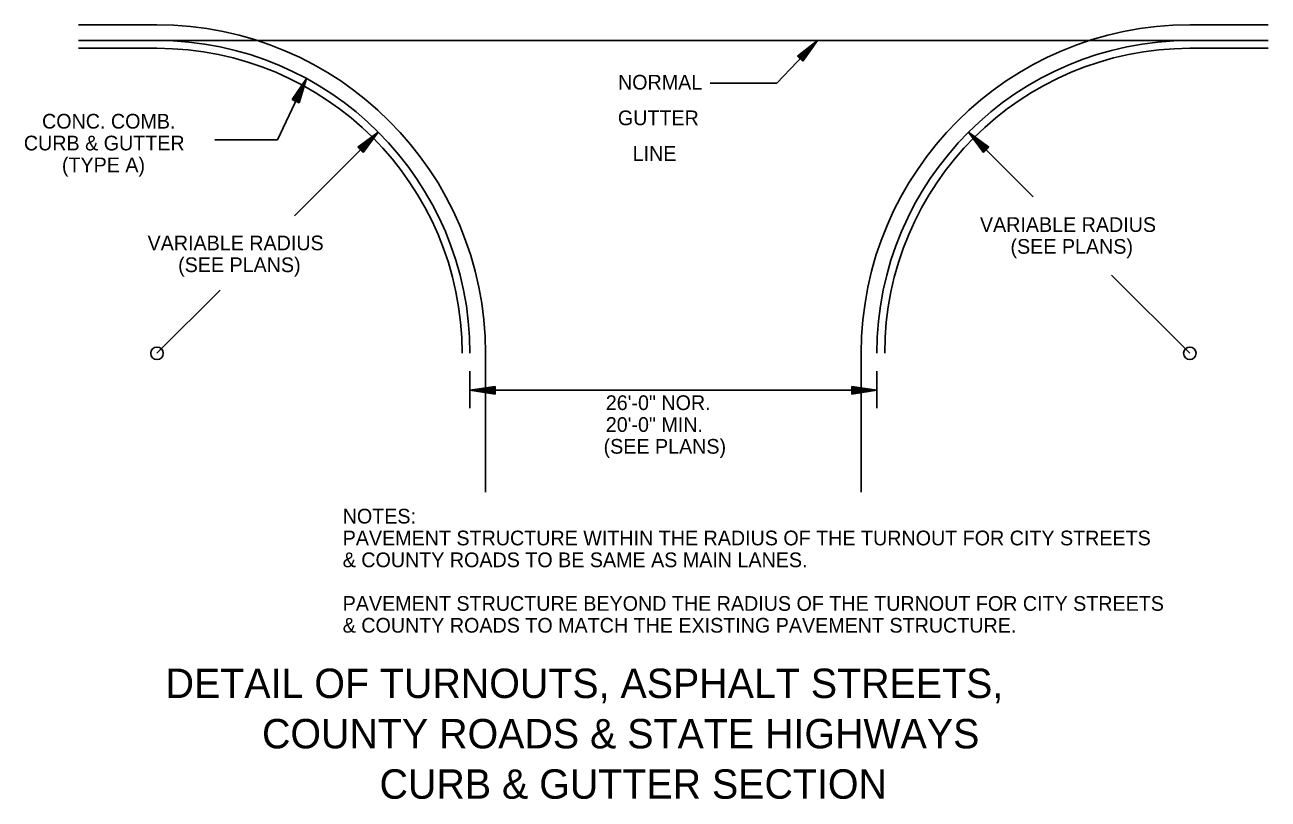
# Model space of a CAD drawing. Extents: x 635488 to 635865, y 290537 to 290973.
# Drawn here: x 635814.4 to 635865.1, y 290707.3 to 290738.9 of the extents above; entities that cross this region are included whole.
import ezdxf

# ---------------------------------------------------------------- set-up
doc = ezdxf.new("R2010")
doc.units = 0
doc.layers.add('Default', color=7, linetype='Continuous')

msp = doc.modelspace()

# ---------------------------------------------------------------- linework, layer by layer
at = {"layer": 'Default'}
for p, q in [((635819.756, 290738.928), (635816.565, 290738.928)), ((635861.865, 290738.928), (635865.054, 290738.928)), ((635840.808, 290738.292), (635816.565, 290738.292)), ((635840.808, 290738.292), (635865.054, 290738.292)), ((635845.024, 290736.544), (635846.685, 290738.292)), ((635845.871, 290737.656), (635846.685, 290738.292)), ((635846.09, 290737.448), (635846.685, 290738.292)), ((635819.756, 290737.973), (635816.565, 290737.973)), ((635845.887, 290737.637), (635846.566, 290738.168)), ((635845.907, 290737.622), (635846.445, 290738.04)), ((635845.925, 290737.602), (635846.329, 290737.917)), ((635845.945, 290737.585), (635846.209, 290737.791)), ((635846.018, 290737.515), (635846.209, 290737.791)), ((635846.036, 290737.499), (635846.329, 290737.917)), ((635846.055, 290737.478), (635846.445, 290738.04)), ((635846.072, 290737.462), (635846.566, 290738.168)), ((635861.865, 290737.973), (635865.054, 290737.973)), ((635845.871, 290737.656), (635846.09, 290737.448)), ((635845.964, 290737.567), (635846.09, 290737.67)), ((635845.996, 290737.533), (635846.09, 290737.67)), ((635824.665, 290734.235), (635825.85, 290736.739)), ((635825.275, 290735.881), (635825.85, 290736.739)), ((635825.301, 290735.872), (635825.777, 290736.588)), ((635825.322, 290735.861), (635825.705, 290736.426)), ((635825.345, 290735.851), (635825.631, 290736.274)), ((635825.484, 290735.787), (635825.631, 290736.274)), ((635825.506, 290735.773), (635825.705, 290736.426)), ((635825.531, 290735.763), (635825.777, 290736.588)), ((635825.554, 290735.752), (635825.85, 290736.739)), ((635842.31, 290736.544), (635845.024, 290736.544)), ((635825.275, 290735.881), (635825.554, 290735.752)), ((635825.37, 290735.841), (635825.556, 290736.118)), ((635825.394, 290735.826), (635825.484, 290735.962)), ((635825.436, 290735.807), (635825.484, 290735.962)), ((635825.462, 290735.795), (635825.556, 290736.118)), ((635822.121, 290734.235), (635824.665, 290734.235)), ((635825.358, 290731.134), (635828.779, 290734.553)), ((635827.946, 290733.939), (635828.778, 290734.554)), ((635827.966, 290733.921), (635828.659, 290734.433)), ((635827.984, 290733.905), (635828.534, 290734.309)), ((635828.129, 290733.759), (635828.534, 290734.309)), ((635828.145, 290733.741), (635828.659, 290734.433)), ((635828.164, 290733.72), (635828.778, 290734.554)), ((635853.457, 290733.72), (635852.841, 290734.554)), ((635853.672, 290733.939), (635852.841, 290734.554)), ((635855.478, 290731.914), (635852.841, 290734.553)), ((635853.473, 290733.741), (635852.961, 290734.433)), ((635853.653, 290733.921), (635852.961, 290734.433)), ((635853.633, 290733.905), (635853.086, 290734.309)), ((635853.492, 290733.759), (635853.086, 290734.309)), ((635827.946, 290733.939), (635828.164, 290733.72)), ((635828.002, 290733.885), (635828.413, 290734.189)), ((635828.02, 290733.866), (635828.291, 290734.066)), ((635828.039, 290733.851), (635828.17, 290733.946)), ((635828.075, 290733.814), (635828.17, 290733.946)), ((635828.091, 290733.798), (635828.291, 290734.066)), ((635828.106, 290733.778), (635828.413, 290734.189)), ((635853.511, 290733.778), (635853.206, 290734.189)), ((635853.618, 290733.885), (635853.206, 290734.189)), ((635853.599, 290733.866), (635853.328, 290734.066)), ((635853.529, 290733.798), (635853.328, 290734.066)), ((635853.579, 290733.851), (635853.45, 290733.946)), ((635853.547, 290733.814), (635853.45, 290733.946)), ((635853.457, 290733.72), (635853.672, 290733.939)), ((635861.865, 290725.53), (635858.675, 290728.718)), ((635819.756, 290725.53), (635822.332, 290728.109)), ((635833.154, 290719.863), (635833.154, 290725.53)), ((635848.466, 290719.863), (635848.466, 290725.53)), ((635832.516, 290723.296), (635832.516, 290724.808)), ((635849.104, 290723.296), (635849.104, 290724.808)), ((635833.538, 290724.175), (635832.516, 290724.024)), ((635833.538, 290724.151), (635832.686, 290724.024)), ((635833.538, 290724.124), (635832.861, 290724.024)), ((635833.538, 290724.099), (635833.031, 290724.024)), ((635833.538, 290723.869), (635833.538, 290724.175)), ((635848.083, 290724.175), (635849.104, 290724.024)), ((635848.083, 290724.175), (635848.083, 290723.869)), ((635848.083, 290724.151), (635848.934, 290724.024)), ((635848.083, 290724.124), (635848.759, 290724.024)), ((635848.083, 290724.099), (635848.59, 290724.024)), ((635849.104, 290724.024), (635832.516, 290724.024)), ((635833.538, 290723.869), (635832.516, 290724.024)), ((635833.538, 290723.895), (635832.686, 290724.024)), ((635833.538, 290723.92), (635832.861, 290724.024)), ((635833.538, 290723.947), (635833.031, 290724.024)), ((635833.538, 290724.07), (635833.203, 290724.024)), ((635833.538, 290723.973), (635833.203, 290724.024)), ((635833.538, 290724.048), (635833.375, 290724.024)), ((635833.538, 290723.998), (635833.375, 290724.024)), ((635848.083, 290724.07), (635848.417, 290724.024)), ((635848.083, 290724.048), (635848.244, 290724.024)), ((635848.083, 290723.869), (635849.104, 290724.024)), ((635848.083, 290723.973), (635848.417, 290724.024)), ((635848.083, 290723.92), (635848.759, 290724.024)), ((635848.083, 290723.895), (635848.934, 290724.024)), ((635848.083, 290723.947), (635848.59, 290724.024)), ((635848.083, 290723.998), (635848.244, 290724.024))]:
    msp.add_line(p, q, dxfattribs=at)
for centre in [(635819.756, 290725.53), (635861.864, 290725.53)]:
    msp.add_circle(centre, 0.255, dxfattribs=at)
for centre, radius, start, end in [((635819.756, 290725.53), 13.398, 0, 90), ((635861.864, 290725.53), 13.398, 90, 180), ((635819.756, 290725.53), 12.76, 0, 90), ((635861.864, 290725.53), 12.76, 90, 180), ((635819.756, 290725.53), 12.441, 0, 90), ((635861.864, 290725.53), 12.441, 90, 179.9971)]:
    msp.add_arc(centre, radius, start, end, dxfattribs=at)

# ---------------------------------------------------------------- texts
for s, height, p in [('NORMAL', 0.6, (635838.551, 290736.289)), ('CONC. COMB.', 0.6, (635815.073, 290734.697)), ('GUTTER', 0.6, (635838.546, 290734.835)), ('CURB & GUTTER', 0.6, (635814.332, 290733.807)), ('LINE', 0.6, (635839.148, 290733.381)), ('(TYPE A)', 0.6, (635815.883, 290732.917)), ('VARIABLE RADIUS', 0.6, (635853.306, 290730.481)), ('VARIABLE RADIUS', 0.6, (635819.375, 290729.732)), ('(SEE PLANS)', 0.6, (635854.551, 290729.591)), ('(SEE PLANS)', 0.6, (635820.62, 290728.842)), ('26\'-0" NOR.', 0.6, (635838.054, 290723.216)), ('20\'-0" MIN.', 0.6, (635838.054, 290722.325)), ('(SEE PLANS)', 0.6, (635837.964, 290721.435)), ('NOTES:', 0.6, (635827.329, 290718.587)), ('PAVEMENT STRUCTURE WITHIN THE RADIUS OF THE TURNOUT FOR CITY STREETS', 0.6, (635827.329, 290717.697)), ('& COUNTY ROADS TO BE SAME AS MAIN LANES.', 0.6, (635827.329, 290716.806)), ('PAVEMENT STRUCTURE BEYOND THE RADIUS OF THE TURNOUT FOR CITY STREETS', 0.6, (635827.329, 290715.026)), ('& COUNTY ROADS TO MATCH THE EXISTING PAVEMENT STRUCTURE.', 0.6, (635827.329, 290714.136)), ('DETAIL OF TURNOUTS, ASPHALT STREETS, ', 1.2, (635820.109, 290711.469)), ('COUNTY ROADS & STATE HIGHWAYS', 1.2, (635824.039, 290709.415)), ('CURB & GUTTER SECTION', 1.2, (635828.831, 290707.361))]:
    msp.add_text(s, height=height, dxfattribs=at).set_placement(p)

doc.saveas('drawing.dxf')
